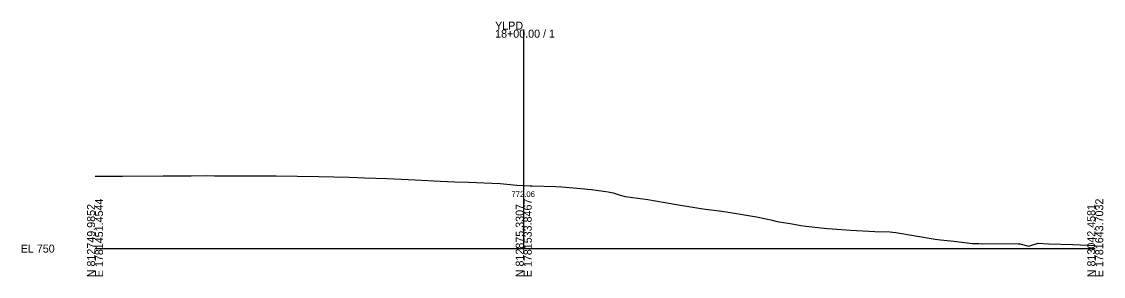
# Model space of a CAD drawing. Extents: x -26 to 353, y -10 to 9080.
# Drawn here: x -25.7 to 352.8, y 7990.3 to 8079.4 of the extents above; entities that cross this region are included whole.
import ezdxf

# ---------------------------------------------------------------- set-up
doc = ezdxf.new("R2010")
doc.units = 0
for name, color, linetype in [('Exist Cross Section Cell', 7, 'Continuous'), ('Exist XS Center Line Elevation Label', 7, 'Continuous'), ('Exist XS Ground Line', 7, 'Continuous')]:
    doc.layers.add(name, color=color, linetype=linetype)

msp = doc.modelspace()

# ---------------------------------------------------------------- linework, layer by layer
at = {"layer": 'Exist Cross Section Cell'}
for p, q in [((150, 8000), (150, 8076.56)), ((0, 8000), (150, 8000)), ((150, 8000), (350, 8000))]:
    msp.add_line(p, q, dxfattribs=at)
at = {"layer": 'Exist XS Ground Line'}
for p, q in [((0, 8025.39), (7.76, 8025.39)), ((7.76, 8025.39), (8.5, 8025.38)), ((8.5, 8025.38), (9.59, 8025.37)), ((9.59, 8025.37), (23.85, 8025.4)), ((23.85, 8025.4), (33.64, 8025.47)), ((33.64, 8025.47), (38.86, 8025.52)), ((38.86, 8025.52), (41.84, 8025.49)), ((41.84, 8025.49), (50.05, 8025.49)), ((50.05, 8025.49), (59.76, 8025.49)), ((59.76, 8025.49), (61.22, 8025.47)), ((61.22, 8025.47), (63.38, 8025.44)), ((63.38, 8025.44), (78.27, 8025.27)), ((78.27, 8025.27), (88.8, 8025)), ((88.8, 8025), (91.87, 8024.9)), ((91.87, 8024.9), (94.29, 8024.8)), ((94.29, 8024.8), (102.21, 8024.51)), ((102.21, 8024.51), (111.98, 8024.03)), ((111.98, 8024.03), (120.76, 8023.62)), ((120.76, 8023.62), (125.87, 8023.41)), ((125.87, 8023.41), (130.64, 8023.18)), ((130.64, 8023.18), (141.72, 8022.77)), ((141.72, 8022.77), (147.65, 8022.16)), ((147.65, 8022.16), (150, 8022.06)), ((150, 8022.06), (152.22, 8021.96)), ((152.22, 8021.96), (152.93, 8021.94)), ((152.93, 8021.94), (161.24, 8021.76)), ((161.24, 8021.76), (163.33, 8021.56)), ((163.33, 8021.56), (169.95, 8021.02)), ((169.95, 8021.02), (173.69, 8020.65)), ((173.69, 8020.65), (179.52, 8019.87)), ((179.52, 8019.87), (181.31, 8019.48)), ((181.31, 8019.48), (183.8, 8018.71)), ((183.8, 8018.71), (185.56, 8018.2)), ((185.56, 8018.2), (188.2, 8017.86)), ((188.2, 8017.86), (193.44, 8017.12)), ((193.44, 8017.12), (201.45, 8015.78)), ((201.45, 8015.78), (202.03, 8015.7)), ((202.03, 8015.7), (202.8, 8015.56)), ((202.8, 8015.56), (210.56, 8014.31)), ((210.56, 8014.31), (213.58, 8013.81)), ((213.58, 8013.81), (219.34, 8013.04)), ((219.34, 8013.04), (221.6, 8012.72)), ((221.6, 8012.72), (222.37, 8012.61)), ((222.37, 8012.61), (231.44, 8011.09)), ((231.44, 8011.09), (236.51, 8010.11)), ((236.51, 8010.11), (238.69, 8009.49)), ((238.69, 8009.49), (243.89, 8008.65)), ((243.89, 8008.65), (246.97, 8008.11)), ((246.97, 8008.11), (248.68, 8007.9)), ((248.68, 8007.9), (253.96, 8007.3)), ((253.96, 8007.3), (256.32, 8007.03)), ((256.32, 8007.03), (257.93, 8006.92)), ((257.93, 8006.92), (264.31, 8006.5)), ((264.31, 8006.5), (272.92, 8006.01)), ((272.92, 8006.01), (278.12, 8005.86)), ((278.12, 8005.86), (280.18, 8005.62)), ((280.18, 8005.62), (294.02, 8003.34)), ((294.02, 8003.34), (295.79, 8003.12)), ((295.79, 8003.12), (300.51, 8002.58)), ((300.51, 8002.58), (307.09, 8001.84)), ((307.09, 8001.84), (309.26, 8001.75)), ((309.26, 8001.75), (323.06, 8001.68)), ((323.06, 8001.68), (323.61, 8001.68)), ((323.61, 8001.68), (326.76, 8000.84)), ((326.76, 8000.84), (330.04, 8001.88)), ((330.04, 8001.88), (333.67, 8001.73)), ((333.67, 8001.73), (342.17, 8001.39)), ((342.17, 8001.39), (350, 8001.05))]:
    msp.add_line(p, q, dxfattribs=at)

# ---------------------------------------------------------------- texts
at = {"layer": 'Exist Cross Section Cell'}
for s, p in [('YLPD', (140, 8076.56)), ('18+00.00 / 1', (140, 8073.76)), ('EL 750', (-26, 7998.6))]:
    msp.add_text(s, height=2.8, dxfattribs=at).set_placement(p)
for s, p in [('E 1781451.4544', (2.8, 7990)), ('N 812749.9852', (0, 7990)), ('N 812875.3307', (150, 7990)), ('E 1781533.8467', (152.8, 7990)), ('N 813042.4581', (350, 7990)), ('E 1781643.7032', (352.8, 7990))]:
    msp.add_text(s, height=2.8, rotation=90, dxfattribs=at).set_placement(p)
at = {"layer": 'Exist XS Center Line Elevation Label'}
msp.add_text('772.06', height=2, dxfattribs=at).set_placement((145.73, 8018.06))

doc.saveas('drawing.dxf')
